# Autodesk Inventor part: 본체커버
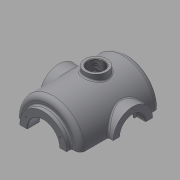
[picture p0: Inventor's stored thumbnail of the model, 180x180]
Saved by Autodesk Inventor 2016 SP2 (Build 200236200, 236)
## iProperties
Created: 2016-02
Part Number: 본체커버
Material: 알루미늄 6061
Document SubType Name: Modeling
Designer: mduedu
Density: 2.71 g/cm^3
Appearance: 기본값
Author: mduedu
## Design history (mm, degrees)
sketch "스케치2"
  geometry: L1 (0, 90)-(0, -90); L2 (65, -65.993)-(65, 90); L3 (65, 90)-(0, 90); A1 r 100 centre (0, 10) between (0, -90) and (65, -65.993); 2 further points
  constraints: 6 end point, 2 point on circle, 1 centre point, 1 coincident, 1 horizontal, 1 midpoint, 1 parallel, 1 point on line, 1 vertical
  dimensions: "d3" = 180 distance of L1.start L1.end; "d5" = 130 diameter of L2 L1; "d6" = 100 radius of A1
revolve "회전1" sketch "스케치2" stored, may be unused: angle "d7" = 90 deg
sketch "스케치3"
  geometry: C1 r 47.5 at (0, 0); 1 further point
  constraints: 1 centre point, 1 coincident
  dimensions: "d8" = 95 diameter of C1
extrude "돌출2" join sketch "스케치3" distance "d10" = 10; taper "d11" = 0 deg
sketch "스케치5"
  geometry: L1 (47.5, 100)-(47.5, 90) reference; L2 (47.5, 90)-(65, 90) reference; L3 (65, 90)-(65, -65.993) reference; L4 (-65, -65.993)-(-65, 90) reference; L5 (-65, 90)-(-47.5, 90) reference; L6 (-47.5, 90)-(-47.5, 100) reference; L7 (-47.5, 100)-(47.5, 100) reference; L8 (55, 75)-(55, -61.239); L9 (0, 75)-(55, 75); L10 (0, 75)-(0, -80); A1 r 100 centre (0, 10) between (-65, -65.993) and (0, -90) reference; A2 r 100 centre (0, 10) between (0, -90) and (65, -65.993) reference; A3 r 90 centre (0, 10) between (0, -80) and (55, -61.239); 1 further point
  constraints: 6 end point, 2 point on circle, 1 centre point, 1 parallel, 1 perpendicular, 1 point on line, 1 vertical
  dimensions: "d13" = 10 distance between parallel lines of L3 L8; "d14" = 10 radial gap between concentric circles of A3 A1; "d15" = 15 distance between parallel lines of L9 L2
revolve "회전2" sketch "스케치5" stored, may be unused: angle "d16" = 90 deg
hole "구멍1" diameter "d19" = 65; stored, may be unused: countersink angle "d23" = 90 deg, drill point angle "d25" = 118 deg; dims "d17" = 10, "d18" = 10, "d20" = 6, "d21" = 4, "d22" = 2, "d24" = 8
node "작업 평면1"
sketch "스케치6"
  geometry: L1 (47.5, 100)-(-47.5, 100) reference; C1 r 40 at (0, -7); 1 further point
  constraints: 1 centre point, 1 vertical alignment
  dimensions: "d27" = 80 diameter of C1; "d29" = 107 distance from line of C1.centre L1
extrude "돌출3" join sketch "스케치6" stored distance "d30" = 10; taper "d31" = 0 deg
hole "구멍2" diameter "d34" = 42; stored, may be unused: countersink angle "d38" = 90 deg, drill point angle "d40" = 118 deg; dims "d32" = 10, "d33" = 10, "d35" = 6, "d36" = 52, "d37" = 18, "d39" = 8
sketch "스케치7" dims "d41" = 65
  geometry: C1 r 40 at (0, 0) reference; 3 further points
  constraints: 2 vertical alignment, 1 coincident, 2 other
hole "구멍3" sketch "스케치7" at (0, 32.5) diameter "d43" = 3.242; stored, may be unused: countersink angle "d47" = 90 deg, drill point angle "d49" = 118 deg; dims "d44" = 11, "d45" = 13, "d46" = 18, "d48" = 13
sketch "스케치8" dims "d53" = 80
  geometry: 3 further points
  constraints: 2 vertical alignment, 1 coincident, 2 other
hole "구멍4" sketch "스케치8" at (0, -40) diameter "d56" = 3.242; stored, may be unused: countersink angle "d60" = 90 deg, drill point angle "d62" = 118 deg; dims "d57" = 11, "d58" = 13, "d59" = 18, "d61" = 13
fillet "모깎기1" dims "d66" = 10
fillet "모깎기2" dims "d67" = 3
fillet "모깎기3" dims "d68" = 0.3
chamfer "모따기1" distance "d69" = 1; stored, may be unused: second distance "d70" = 2, angle "d71" = 45 deg
node "작업 평면5"
sketch "스케치10"
  geometry: L1 (-50, 66)-(50, 66); L2 (50, 66)-(50, 50); L3 (50, 50)-(-50, 50); L4 (-50, 50)-(-50, 66); 2 further points
  constraints: 8 end point, 2 horizontal, 2 vertical, 1 midpoint, 1 vertical alignment
  dimensions: "d177" = 50 distance from line of L3 point (0, 0); "d178" = 100 distance of L1.start L1.end; "d179" = 16 distance of L3.end L1.start
extrude "돌출5" join sketch "스케치10" stored distance "d84" = 10; taper "d85" = 0 deg
sketch "스케치21" dims "d180" = 220, "d182" = 130
  geometry: L1 (65, 58)-(-65, 58); L2 (-65, 58)-(-65, -32); L3 (-65, -32)-(65, -32); L4 (65, -32)-(65, 58); L5 (50, 50)-(50, 66) reference; 4 further points
  constraints: 8 end point, 3 horizontal alignment, 3 midpoint, 2 parallel, 1 horizontal, 1 perpendicular, 1 vertical alignment, 4 other
extrude "돌출13" join sketch "스케치21" distance "d183" = 10; taper "d184" = 0 deg
sketch "스케치11"
  geometry: L1 (-65, 80)-(-65, -61.239) reference; L2 (-100, -97)-(-100, -32) reference; L3 (-65, -42.793)-(-100, -63); L4 (-100, -97)-(-110, -97) reference; 1 further point
  constraints: 2 end point, 2 point on line
  dimensions: "d185" = 34 distance from line of L3.end L4; "d186" = 120 deg angle of L2 L3
feature "리브1" sketch "스케치11" dims "d88" = 1, "d89" = 16, "d90" = 0, "d91" = 0, "d92" = 1, "d93" = 1
fillet "모깎기12"
fillet "모깎기13"
fillet "모깎기16" dims "d167" = 3
fillet "모깎기18"
fillet "모깎기17" dims "d168" = 3
fillet "모깎기19" dims "d187" = 3
node "작업 평면6"
sketch "스케치19"
  geometry: L1 (75, -47)-(75, 33) reference; L2 (-75, -47)-(-75, 33) reference; L3 (75, -7)-(-75, -7); C1 r 22.5 at (0, -7); 1 further point
  constraints: 3 midpoint, 2 end point, 1 centre point
  dimensions: "d149" = 45 diameter of C1
extrude "돌출11" join sketch "스케치19" stored distance "d150" = 10; taper "d151" = 0 deg
hole "구멍6" diameter "d154" = 33.376; stored, may be unused: countersink angle "d158" = 90 deg, drill point angle "d160" = 118 deg; dims "d155" = 6, "d156" = 4, "d157" = 2, "d159" = 8, "d190" = 10, "d191" = 10
fillet "모깎기11" dims "d161" = 3
chamfer "모따기3" distance "d164" = 1; stored, may be unused: second distance "d165" = 2, angle "d166" = 45 deg
sketch "스케치22" dims "d189" = 20
  geometry: L1 (-10, -123)-(10, -123); L2 (10, -123)-(10, -103); L3 (10, -103)-(-10, -103); L4 (-10, -103)-(-10, -123); A1 r 65 centre (0, -58) between (-65, -58) and (65, -58) reference; 2 further points
  constraints: 8 end point, 2 parallel, 1 horizontal, 1 horizontal alignment, 1 midpoint, 1 perpendicular, 1 tangent, 1 vertical alignment, 2 other
  dimensions: "d193" = 30 dimension on L1
extrude "돌출14" cut sketch "스케치22" stored distance "d194" = 10; taper "d195" = 0 deg
fillet "모깎기21" dims "d196" = 3
feature "분할1"
node "솔리드2"
pattern_circular "원형 패턴1" dims angle "d51" = 360 deg
mirror "대칭1"
pattern_circular "원형 패턴2" dims angle "d64" = 360 deg
node "절단 모서리 투영1"
other parameters: "d26" = 75, "d136" = 175
